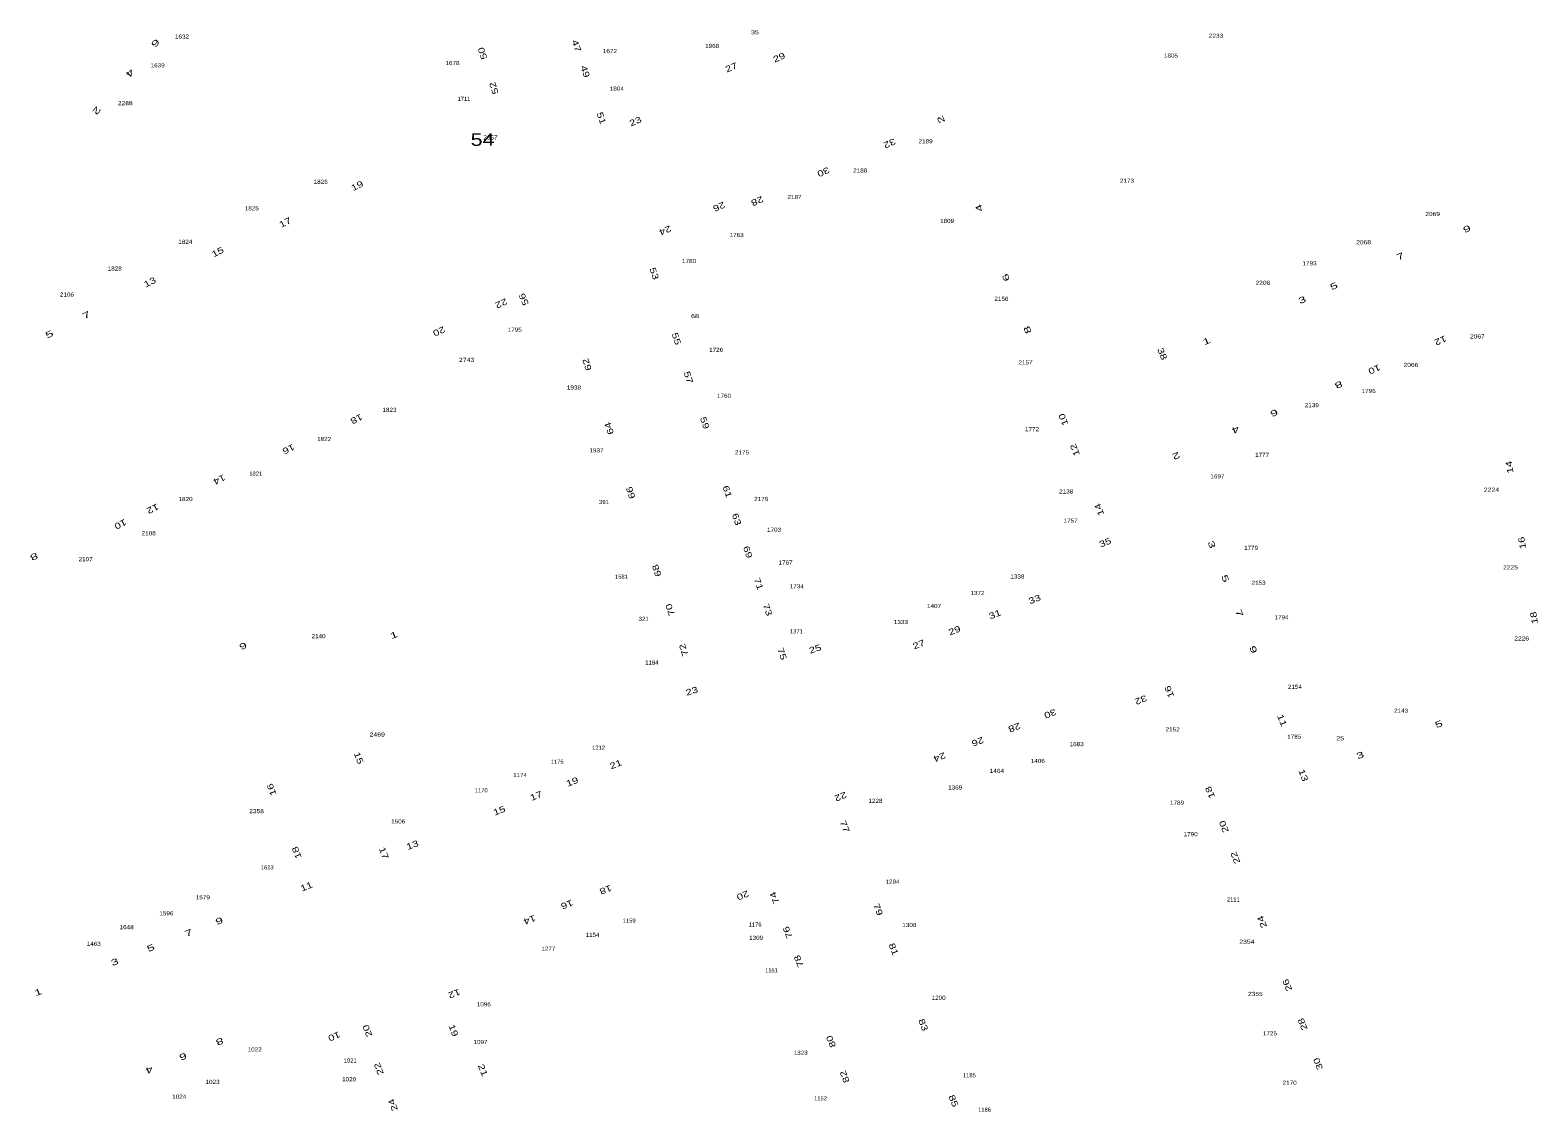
# Model space of a CAD drawing. Extents: x -828673 to -815583, y -1077737 to -1063807.
# Drawn here: x -821440 to -821074.1, y -1071841 to -1071578.4 of the extents above; entities that cross this region are included whole.
import ezdxf
from ezdxf.enums import TextEntityAlignment as Align

# ---------------------------------------------------------------- set-up
doc = ezdxf.new("R2010")
doc.units = 0
doc.header["$LTSCALE"] = 0.4
doc.layers.add('1', color=7, linetype='Continuous')
doc.layers.add('2', color=7, linetype='Continuous')

msp = doc.modelspace()

# ---------------------------------------------------------------- texts
at = {"layer": '1'}
for s, width, p in [('1632', 1.15, (-821403.179, -1071580.475)), ('35', 1.3, (-821264.142, -1071579.434)), ('2233', 1.2, (-821152.246, -1071580.27)), ('1672', 1.15, (-821299.33, -1071583.998)), ('1968', 1.15, (-821274.522, -1071582.747)), ('1639', 1.15, (-821409.077, -1071587.454)), ('1678', 1.15, (-821337.54, -1071586.895)), ('1805', 1.15, (-821163.179, -1071585.1)), ('1804', 1.15, (-821297.65, -1071593.105)), ('2288', 1.2, (-821416.942, -1071596.633)), ('2857', 1.15, (-821328.32, -1071604.98)), ('2189', 1.15, (-821222.729, -1071605.887)), ('2188', 1.15, (-821238.591, -1071613.005)), ('1826', 1.15, (-821369.518, -1071615.734)), ('2173', 1.15, (-821173.859, -1071615.469)), ('2187', 1.15, (-821254.536, -1071619.411)), ('1825', 1.15, (-821386.233, -1071622.171)), ('2069', 1.2, (-821099.682, -1071623.547)), ('1809', 1.15, (-821217.498, -1071625.231)), ('1824', 1.15, (-821402.364, -1071630.3)), ('1763', 1.15, (-821268.577, -1071628.664)), ('2068', 1.2, (-821116.425, -1071630.407)), ('1780', 1.15, (-821280.124, -1071634.961)), ('1828', 1.15, (-821419.504, -1071636.788)), ('1793', 1.15, (-821129.555, -1071635.512)), ('2206', 1.2, (-821140.877, -1071640.245)), ('2106', 1.15, (-821431.11, -1071643.099)), ('2156', 1.15, (-821204.317, -1071644.134)), ('68', 1.3, (-821278.674, -1071648.318)), ('1795', 1.15, (-821322.429, -1071651.647)), ('2067', 1.2, (-821088.837, -1071653.274)), ('1726', 1.15, (-821273.556, -1071656.53)), ('2743', 1.25, (-821334.095, -1071658.955)), ('2157', 1.15, (-821198.479, -1071659.573)), ('2066', 1.2, (-821104.944, -1071660.188)), ('1938', 1.15, (-821308.064, -1071665.676)), ('1760', 1.15, (-821271.63, -1071667.667)), ('1796', 1.15, (-821115.203, -1071666.516)), ('1823', 1.15, (-821352.833, -1071671.084)), ('2139', 1.15, (-821129.002, -1071669.948)), ('1822', 1.15, (-821368.693, -1071678.184)), ('1772', 1.15, (-821196.894, -1071675.784)), ('1937', 1.15, (-821302.597, -1071680.92)), ('2175', 1.15, (-821267.281, -1071681.424)), ('1777', 1.15, (-821141.068, -1071682.02)), ('1821', 1.05, (-821385.281, -1071686.567)), ('1697', 1.15, (-821151.912, -1071687.232)), ('1820', 1.15, (-821402.312, -1071692.75)), ('391', 1.1, (-821300.758, -1071693.452)), ('2176', 1.15, (-821262.596, -1071692.71)), ('2138', 1.15, (-821188.608, -1071690.899)), ('2224', 1.25, (-821085.404, -1071690.477)), ('2108', 1.15, (-821411.247, -1071701.048)), ('1703', 1.15, (-821259.499, -1071700.205)), ('1757', 1.15, (-821187.521, -1071697.986)), ('1779', 1.15, (-821143.731, -1071704.588)), ('2107', 1.15, (-821426.552, -1071707.335)), ('1767', 1.15, (-821256.71, -1071708.148)), ('1581', 1.05, (-821296.534, -1071711.586)), ('1338', 1.15, (-821200.453, -1071711.552)), ('2225', 1.2, (-821080.765, -1071709.322)), ('1734', 1.15, (-821253.99, -1071713.926)), ('1372', 1.15, (-821210.131, -1071715.559)), ('2153', 1.15, (-821141.924, -1071713.044)), ('1407', 1.15, (-821220.677, -1071718.699)), ('321', 1.1, (-821291.147, -1071721.809)), ('1333', 1.15, (-821228.712, -1071722.593)), ('1794', 1.15, (-821136.343, -1071721.447)), ('2140', 1.15, (-821370.03, -1071726.031)), ('1371', 1.05, (-821254.074, -1071724.854)), ('2226', 1.2, (-821078.074, -1071726.589)), ('1184', 1.1, (-821289.138, -1071732.416)), ('2154', 1.15, (-821133.1, -1071738.318)), ('2143', 1.15, (-821107.32, -1071744.115)), ('2152', 1.15, (-821162.771, -1071748.661)), ('2469', 1.25, (-821355.793, -1071749.908)), ('1683', 1.15, (-821186.061, -1071752.238)), ('1785', 1.15, (-821133.26, -1071750.444)), ('25', 1.3, (-821122.104, -1071750.816)), ('1212', 1.05, (-821302.074, -1071753.08)), ('1174', 1.1, (-821321.141, -1071759.71)), ('1175', 1.05, (-821312.121, -1071756.502)), ('1464', 1.2, (-821205.434, -1071758.728)), ('1406', 1.15, (-821195.501, -1071756.311)), ('1170', 1.05, (-821330.547, -1071763.431)), ('1369', 1.15, (-821215.544, -1071762.757)), ('1228', 1.15, (-821234.901, -1071766.003)), ('1789', 1.15, (-821161.704, -1071766.451)), ('2358', 1.2, (-821385.088, -1071768.513)), ('1506', 1.15, (-821350.705, -1071770.995)), ('1790', 1.15, (-821158.393, -1071774.105)), ('1613', 1.05, (-821382.494, -1071782.15)), ('1294', 1.15, (-821230.74, -1071785.609)), ('1579', 1.15, (-821398.111, -1071789.429)), ('1596', 1.15, (-821406.964, -1071793.304)), ('1159', 1.05, (-821294.657, -1071795.084)), ('1176', 1.05, (-821264.097, -1071796.027)), ('1308', 1.15, (-821226.674, -1071796.136)), ('1648', 1.15, (-821416.615, -1071796.665)), ('1154', 1.1, (-821303.542, -1071798.545)), ('1309', 1.15, (-821263.846, -1071799.25)), ('1463', 1.15, (-821424.603, -1071800.704)), ('1277', 1.15, (-821314.264, -1071801.879)), ('2354', 1.25, (-821144.749, -1071800.206)), ('1200', 1.15, (-821219.56, -1071813.817)), ('2355', 1.2, (-821142.691, -1071812.873)), ('1096', 1.15, (-821329.937, -1071815.398)), ('1097', 1.15, (-821330.749, -1071824.544)), ('1725', 1.15, (-821139.157, -1071822.452)), ('1022', 1.15, (-821385.527, -1071826.347)), ('1021', 1.05, (-821362.346, -1071829.039)), ('1323', 1.15, (-821253.038, -1071827.159)), ('1185', 1.05, (-821212.097, -1071832.621)), ('1023', 1.15, (-821395.752, -1071834.216)), ('1020', 1.15, (-821362.609, -1071833.575)), ('2170', 1.15, (-821134.37, -1071834.427)), ('1024', 1.15, (-821403.843, -1071837.807)), ('1152', 1.05, (-821248.218, -1071838.234)), ('1186', 1.05, (-821208.428, -1071840.991))]:
    msp.add_text(s, height=1, dxfattribs=dict(at, width=width)).set_placement(p, align=Align.CENTER)
for s, p in [('1711', (-821334.731, -1071595.606)), ('2111', (-821148.058, -1071789.951)), ('1151', (-821260.129, -1071807.157))]:
    msp.add_text(s, height=1, dxfattribs=at).set_placement(p, align=Align.CENTER)
at = {"layer": '2'}
for s, rotation, width, p in [('6', 229.001, 1.75, (-821410.1899, -1071581.075)), ('50', 108.716, 1.35, (-821329.5311, -1071583.8222)), ('47', 289.39, 1.35, (-821308.1439, -1071582.462)), ('27', 23.864, 1.35, (-821269.5729, -1071588.1427)), ('29', 23.793, 1.35, (-821257.9696, -1071585.7206)), ('4', 228.912, 1.75, (-821416.3701, -1071588.3801)), ('49', 288.306, 1.35, (-821306.0404, -1071588.6764)), ('52', 108.435, 1.35, (-821326.7669, -1071592.2522)), ('2', 228.988, 1.75, (-821424.4225, -1071597.4683)), ('51', 288.402, 1.35, (-821302.093, -1071600.0187)), ('23', 23.862, 1.35, (-821292.8574, -1071601.237)), ('2', 113.6, 1.65, (-821218.3063, -1071599.8228)), ('32', 203.639, 1.35, (-821231.7593, -1071605.2158)), ('30', 203.768, 1.35, (-821247.8297, -1071612.1668)), ('19', 27.044, 1.35, (-821360.3275, -1071616.8746)), ('28', 203.763, 1.35, (-821263.8778, -1071619.2327)), ('26', 203.789, 1.35, (-821273.1455, -1071620.5883)), ('4', 111.683, 1.65, (-821209.0423, -1071621.3411)), ('17', 27.055, 1.35, (-821377.8006, -1071625.7723)), ('24', 203.123, 1.35, (-821286.2015, -1071626.3637)), ('9', 23.143, 1.65, (-821091.0823, -1071627.3578)), ('15', 27.027, 1.35, (-821394.1653, -1071632.943)), ('7', 23.083, 1.65, (-821107.2406, -1071634.0066)), ('53', 288.592, 1.35, (-821289.284, -1071637.7359)), ('6', 111.68, 1.65, (-821202.5332, -1071638.2011)), ('13', 27.099, 1.35, (-821410.6301, -1071640.2632)), ('5', 23.683, 1.65, (-821123.3478, -1071641.2342)), ('22', 204.084, 1.35, (-821325.9819, -1071644.0647)), ('56', 113.931, 1.35, (-821319.5521, -1071643.4742)), ('3', 23.715, 1.65, (-821131.0546, -1071644.5846)), ('7', 27.118, 1.7, (-821426.0364, -1071648.256)), ('5', 27.566, 1.7, (-821435.0196, -1071652.9078)), ('20', 203.602, 1.35, (-821341.0902, -1071650.8497)), ('55', 288.706, 1.35, (-821283.8852, -1071653.563)), ('8', 111.783, 1.65, (-821197.3047, -1071650.9088)), ('12', 203.741, 1.35, (-821098.0495, -1071653.0664)), ('38', 292.612, 1.35, (-821165.9819, -1071657.2711)), ('1', 22.413, 1.65, (-821154.2875, -1071654.5932)), ('62', 108.653, 1.35, (-821304.1824, -1071659.3669)), ('10', 203.719, 1.35, (-821114.1023, -1071660.0857)), ('57', 288.397, 1.35, (-821280.9581, -1071662.9448)), ('8', 203.86, 1.65, (-821122.7916, -1071663.8267)), ('6', 203.732, 1.65, (-821138.4507, -1071670.6614)), ('18', 206.968, 1.35, (-821361.1414, -1071672.1436)), ('64', 108.69, 1.35, (-821298.8005, -1071674.8648)), ('59', 288.751, 1.35, (-821277.0221, -1071673.9984)), ('10', 111.239, 1.35, (-821188.5916, -1071672.6897)), ('4', 203.378, 1.65, (-821147.8069, -1071674.753)), ('16', 206.96, 1.35, (-821377.6435, -1071679.4574)), ('12', 111.587, 1.35, (-821185.7903, -1071680.0584)), ('2', 203.184, 1.65, (-821162.2117, -1071681.0809)), ('14', 99.106, 1.35, (-821080.29, -1071684.3967)), ('14', 206.847, 1.35, (-821394.4443, -1071686.8555)), ('66', 108.15, 1.35, (-821293.5826, -1071690.4776)), ('61', 288.644, 1.35, (-821271.5388, -1071690.6692)), ('12', 206.468, 1.35, (-821410.5797, -1071693.9335)), ('63', 288.666, 1.35, (-821269.2813, -1071697.385)), ('14', 111.272, 1.35, (-821179.8886, -1071694.5556)), ('10', 207.22, 1.35, (-821418.4439, -1071697.7049)), ('69', 288.435, 1.35, (-821266.5631, -1071705.3418)), ('35', 21.296, 1.35, (-821178.8659, -1071703.4839)), ('3', 291.634, 1.65, (-821153.9795, -1071703.549)), ('16', 99.474, 1.35, (-821077.2306, -1071702.7764)), ('8', 206.469, 1.7, (-821439.3997, -1071705.5701)), ('68', 108.435, 1.35, (-821287.2639, -1071709.3812)), ('5', 291.682, 1.65, (-821150.6887, -1071711.8099)), ('71', 288.653, 1.35, (-821263.9456, -1071713.0471)), ('70', 109.125, 1.35, (-821284.0124, -1071718.8942)), ('73', 288.459, 1.35, (-821261.7685, -1071719.3385)), ('33', 21.448, 1.35, (-821195.9832, -1071717.2601)), ('31', 21.565, 1.35, (-821205.6352, -1071720.9222)), ('7', 291.66, 1.65, (-821147.2862, -1071720.2127)), ('18', 99.098, 1.35, (-821074.3508, -1071720.9716)), ('1', 21.584, 1.65, (-821351.4914, -1071725.9552)), ('29', 21.644, 1.35, (-821215.4336, -1071724.8341)), ('6', 201.956, 1.65, (-821388.6416, -1071727.2396)), ('72', 108.422, 1.35, (-821280.7175, -1071728.6465)), ('75', 288.905, 1.35, (-821258.2511, -1071730.0575)), ('25', 18.683, 1.35, (-821249.2903, -1071729.3299)), ('27', 21.415, 1.35, (-821224.0953, -1071728.2267)), ('9', 291.388, 1.65, (-821143.8863, -1071729.0415)), ('23', 18.53, 1.35, (-821279.2139, -1071739.5566)), ('32', 201.546, 1.35, (-821170.7506, -1071740.3136)), ('16', 111.549, 1.35, (-821162.8784, -1071738.763)), ('30', 201.545, 1.35, (-821192.7436, -1071743.6666)), ('28', 201.383, 1.35, (-821201.4446, -1071747.0143)), ('11', 291.99, 1.35, (-821136.8966, -1071746.2312)), ('5', 21.542, 1.65, (-821097.9204, -1071747.5679)), ('26', 201.107, 1.35, (-821210.3489, -1071750.4595)), ('15', 291.3, 1.35, (-821360.9848, -1071755.3681)), ('24', 201.934, 1.35, (-821219.6088, -1071754.2241)), ('3', 21.75, 1.65, (-821117.0034, -1071755.1167)), ('21', 21.304, 1.35, (-821297.6425, -1071757.3335)), ('13', 291.329, 1.35, (-821131.7369, -1071759.5572)), ('16', 111.03, 1.35, (-821380.7255, -1071762.5206)), ('19', 21.678, 1.35, (-821308.203, -1071761.5653)), ('18', 112.419, 1.35, (-821153.0043, -1071763.18)), ('17', 21.578, 1.35, (-821316.9663, -1071764.9869)), ('22', 201.725, 1.35, (-821243.6189, -1071763.78)), ('15', 21.517, 1.35, (-821325.9016, -1071768.5803)), ('77', 291.493, 1.35, (-821243.0299, -1071771.9947)), ('20', 111.007, 1.35, (-821149.6349, -1071771.5154)), ('18', 111.667, 1.35, (-821374.6474, -1071777.8189)), ('17', 291.749, 1.35, (-821354.8675, -1071778.4646)), ('13', 21.149, 1.35, (-821347.0006, -1071776.9186)), ('22', 111.801, 1.35, (-821146.8648, -1071779.035)), ('11', 22.214, 1.35, (-821372.6955, -1071787.0039)), ('18', 201.566, 1.35, (-821300.6228, -1071786.3908)), ('20', 201.69, 1.35, (-821267.3488, -1071787.764)), ('74', 111.549, 1.35, (-821258.6895, -1071788.808)), ('16', 201.664, 1.35, (-821310.0211, -1071789.9823)), ('79', 291.636, 1.35, (-821234.9313, -1071792.1365)), ('9', 21.379, 1.65, (-821393.8644, -1071795.3544)), ('14', 201.689, 1.35, (-821319.0768, -1071793.6999)), ('24', 111.827, 1.35, (-821140.3806, -1071794.6169)), ('7', 21.856, 1.65, (-821401.2697, -1071798.2469)), ('76', 111.445, 1.35, (-821255.4908, -1071797.1932)), ('5', 21.779, 1.65, (-821410.4828, -1071801.9013)), ('81', 291.594, 1.35, (-821231.1743, -1071801.783)), ('3', 21.257, 1.65, (-821419.2494, -1071805.3106)), ('78', 111.951, 1.35, (-821252.8027, -1071804.1599)), ('26', 111.801, 1.35, (-821134.2508, -1071809.97)), ('1', 21.217, 1.65, (-821437.8269, -1071812.6301)), ('12', 201.584, 1.35, (-821337.3556, -1071811.6193)), ('20', 111.948, 1.35, (-821357.4836, -1071821.0738)), ('19', 291.435, 1.35, (-821337.9852, -1071821.4954)), ('83', 291.397, 1.35, (-821223.9763, -1071820.1664)), ('28', 111.404, 1.35, (-821130.5358, -1071819.4607)), ('8', 201.668, 1.65, (-821394.3041, -1071823.2401)), ('10', 202.598, 1.35, (-821366.5263, -1071821.9967)), ('80', 112.237, 1.35, (-821244.9868, -1071823.6483)), ('6', 202.328, 1.65, (-821403.2026, -1071826.8893)), ('30', 111.59, 1.35, (-821126.7866, -1071829.085)), ('4', 201.189, 1.65, (-821411.3794, -1071830.1416)), ('22', 111.288, 1.35, (-821354.7219, -1071830.2898)), ('21', 291.801, 1.35, (-821330.8482, -1071831.152)), ('82', 111.475, 1.35, (-821241.6577, -1071832.2021)), ('24', 111.351, 1.35, (-821351.2864, -1071839.0696)), ('85', 291.335, 1.35, (-821216.648, -1071838.6116))]:
    msp.add_text(s, height=1.5, rotation=rotation, dxfattribs=dict(at, width=width)).set_placement(p, align=Align.CENTER)
at = {"layer": '2', "width": 1.3}
msp.add_text('54', height=3, dxfattribs=at).set_placement((-821330.23, -1071606.5), align=Align.CENTER)

doc.saveas('drawing.dxf')
